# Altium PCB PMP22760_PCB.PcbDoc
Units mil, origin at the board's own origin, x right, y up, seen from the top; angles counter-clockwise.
Board outline 2440.94 x 1102.36 mil, 2 copper layers (Top Layer, Bottom Layer), stack 62 mil thick; 50 components, 22 nets, 102 pads, 106 vias.
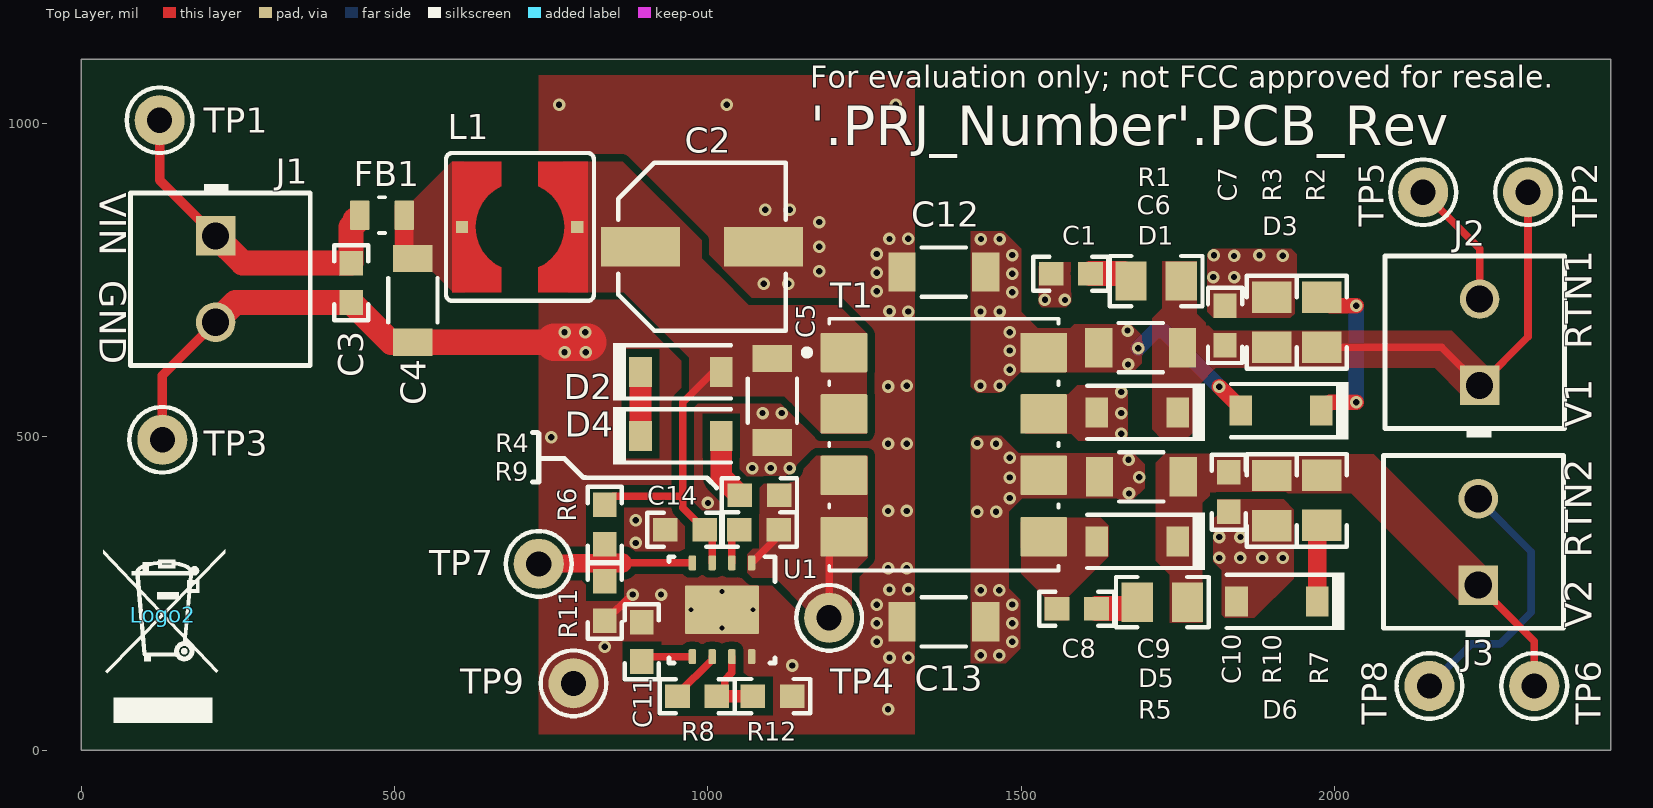
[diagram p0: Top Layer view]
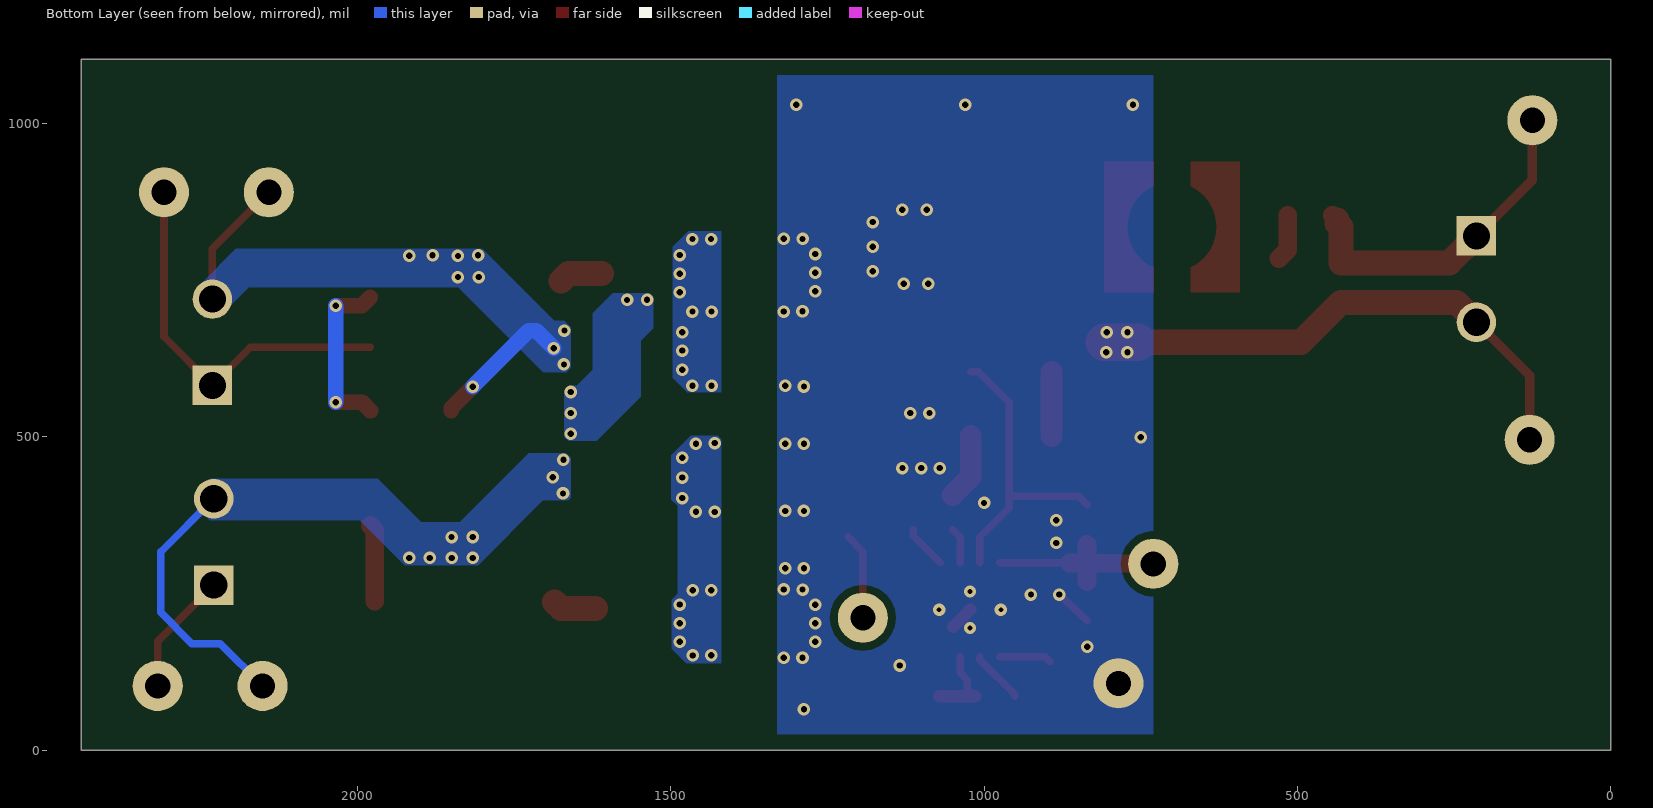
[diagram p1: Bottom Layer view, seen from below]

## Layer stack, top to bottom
Top Solder: solder mask 0.4, Solder Resist, Dk 3.5
Top Layer: signal copper 1.4
Dielectric1: core 59.2, FR-4, Dk 4.8
Bottom Layer: signal copper 1.4
Bottom Solder: solder mask 0.4, Solder Resist, Dk 3.5

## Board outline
0,0 2440.94,0 2440.94,1102.36 0,1102.36

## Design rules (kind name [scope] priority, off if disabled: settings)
AcuteAngle [All] p1: minimum=4.50000000000000E+0001 checktracksonly=FALSE
AssemblyTestPointUsage [All] p1: valid=2
BoardOutlineClearance BoardOutlineClearance_MountingHoles [OnCopper and InComponentClass('Mounting Holes')] p1: gap=39.37 ignorepadtopadclearanceinfootprint=FALSE
BoardOutlineClearance BoardOutlineClearance_Poly [OnCopper and IsPoly] p2: gap=25 ignorepadtopadclearanceinfootprint=FALSE
BoardOutlineClearance [OnCopper and Not InComponentClass('Logo') and not InComponentClass('FiducialMark') and not InRegion(1000,500,4000,800) and not InPoly] p3: gap=50 ignorepadtopadclearanceinfootprint=FALSE
Clearance Clearance_Keepouts [((IsTrack Or IsArc) And Not InPoly) And IsFree and IsKeepOut vs ((IsTrack Or IsArc) And Not InPoly) And IsFree and IsKeepOut] p1: gap=0 ignorepadtopadclearanceinfootprint=FALSE
Clearance Clearance_Poly [InPolygon] p2: gap=12 ignorepadtopadclearanceinfootprint=TRUE
Clearance Clearance_FiducialMark [IsKeepOut and InComponentClass('FiducialMark') vs IsPad and InComponentClass('FiducialMark')] p3: gap=0 ignorepadtopadclearanceinfootprint=FALSE
Clearance [All] p4: gap=7.87 ignorepadtopadclearanceinfootprint=TRUE
ComponentClearance ComponentClearance_MountingHoles_FiducialMarks [InComponentClass('Mounting Holes') vs InComponentClass('FiducialMark')] p1: gap=50 collisioncheckmode=3 verticalgap=10 showdistances=FALSE
ComponentClearance ComponentClearance_Shunt [InComponentClass('Header') vs InComponentClass('Shunt')] p2: gap=0 collisioncheckmode=3 verticalgap=0 showdistances=FALSE
ComponentClearance ComponentClearance_Logo [InComponentClass('Logo')] p3: gap=50 collisioncheckmode=3 verticalgap=10 showdistances=FALSE
ComponentClearance ComponentClearance_ScrewToNut [(HasFootprint('NY PMS 440 0025 PH')) vs (HasFootprint('Keystone_1902C'))] p4: gap=5 collisioncheckmode=3 verticalgap=10 showdistances=FALSE
ComponentClearance ComponentClearance_MountingHoles [InComponentClass('Mounting Holes')] p5: gap=250 collisioncheckmode=3 verticalgap=100000 showdistances=FALSE
ComponentClearance ComponentClearance_SmallPassives [HasFootprint('0201*') or HasFootprint('0402*') or HasFootprint('0508') or HasFootprint('0603*') or HasFootprint('0612') or HasFootprint('0805*') or HasFootprint('0815*') or HasFootprint('0830*') or HasFootprint('1206*') or HasFootprint('1210*') or HasFootprint('1808*') or HasFootprint('1812*') or HasFootprint('1825*') or HasFootprint('2010*') or HasFootprint('2220*') or HasFootprint('2225*') or HasFootprint('2512*') or HasFootprint('2728*') or HasFootprint('3518*') vs HasFootprint('0201*') or HasFootprint('0402*') or HasFootprint('0508') or HasFootprint('0603*') or HasFootprint('0612') or HasFootprint('0805*') or HasFootprint('0815*') or HasFootprint('0830*') or HasFootprint('1206*') or HasFootprint('1210*') or HasFootprint('1808*') or HasFootprint('1812*') or HasFootprint('1825*') or HasFootprint('2010*') or HasFootprint('2220*') or HasFootprint('2225*') or HasFootprint('2512*') or HasFootprint('2728*') or HasFootprint('3518*')] p6: gap=14.96 collisioncheckmode=3 verticalgap=10 showdistances=FALSE
ComponentClearance ComponentClearance_THtoSMT [IsThruComponent vs IsSMTComponent] p7: gap=40 collisioncheckmode=3 verticalgap=30 showdistances=FALSE
ComponentClearance ComponentClearance_THtoTH [IsThruComponent vs IsThruComponent] p8: gap=30 collisioncheckmode=3 verticalgap=30 showdistances=FALSE
ComponentClearance [All] p9: gap=30 collisioncheckmode=3 verticalgap=10 showdistances=FALSE
DiffPairsRouting [All] p1: maxlimit=100 minlimit=10 mostfreqgap=10 toplayer_minwidth=15 toplayer_maxwidth=15 toplayer_prefwidth=15 bottomlayer_minwidth=15 bottomlayer_maxwidth=15 bottomlayer_prefwidth=15 maxuncoupledlength=1000
FabricationTestPointUsage TestPointUsage [All] p1: valid=2 allowmultiple=FALSE
FabricationTestpoint Testpoint [All] p1: side=3 testpointundercomponent=TRUE minsize=40 maxsize=100 preferedsize=60 minholesize=0 maxholesize=40 preferedholesize=32 testpointgrid=1 allowsidetop=TRUE allowsidebottom=TRUE usegrid=TRUE gridtolerance=0.01
FanoutControl Fanout_LCC [IsLCC] p1: bgadir=Out bgaviamode=Centered fanoutstyle=Auto fanoutdirection=Alternating viagrid=1 // Fanout_LCC (Default Rule)
FanoutControl Fanout_BGA [IsBGA] p2: bgadir=Out bgaviamode=Centered fanoutstyle=Auto fanoutdirection=Alternating viagrid=1 // Fanout_BGA (Default Rule)
FanoutControl Fanout_Default [All] p4: bgadir=Out bgaviamode=Centered fanoutstyle=Auto fanoutdirection=Alternating viagrid=1 // Fanout_Default (Default Rule)
FanoutControl Fanout_Small [(CompPinCount < 5)] p5: bgadir=Out bgaviamode=Centered fanoutstyle=Auto fanoutdirection=OutThenIn viagrid=1 // Fanout_Small (Default Rule)
HoleSize [All] p1: absolutevalues=TRUE maxlimit=251 minlimit=7.87 maxpercent=80.000 minpercent=20.000
MinimumAnnularRing MinimumAnnularRing_ThermalPadVias [IsVia and InAnyComponent] p1: minimumring=5.91
MinimumAnnularRing [All] p2: minimumring=5
MinimumSolderMaskSliver MinimumSolderMaskSliver_Logo [InComponentClass('Logo') vs InComponentClass('Logo')] p1: minsoldermaskwidth=0.7
MinimumSolderMaskSliver [All] p2: minsoldermaskwidth=3.94
PlaneClearance [All] p1: clearance=12
PlaneConnect [All] p1: planeconnectstyle=Direct reliefexpansion=10 reliefentries=4 reliefconductorwidth=10 reliefairgap=10
PolygonConnect [All] p1: connectstyle=Direct reliefconductorwidth=10 reliefentries=4 polygonreliefangle="90 Angle" airgapwidth=10
RoutingVias ThermalPadVias [IsVia and InAnyComponent] p1: holewidth=7.87 width=19.68 viastyle="Through Hole" minholewidth=7.87 minwidth=19 maxholewidth=12.99 maxwidth=23.62
RoutingVias [All] p2: holewidth=16 width=34 viastyle="Through Hole" minholewidth=7.87 minwidth=19 maxholewidth=40 maxwidth=65
SilkToBoardRegionClearance [Not ((IsComment or IsDesignator) And (Hide <> 'False')) and not InRegion(1000,500,4000,800)] p1:
SilkToSilkClearance SilkToSilkClearance_Pb-FreeLogo [(HasFootprint('Pb-Free_Overlay_Medium') OR HasFootprint('Pb-Free_Overlay_Small')) vs (HasFootprint('Pb-Free_Overlay_Medium') OR HasFootprint('Pb-Free_Overlay_Small'))] p1: silktosilkclearance=0
SilkToSilkClearance [All] p2: silktosilkclearance=0
SilkToSolderMaskClearance SilkToComponentPadClearance [(IsPad or IsFill or IsRegion) and InAnycomponent] p1: minsilkscreentomaskgap=0 clearancetoexposedcopper=TRUE
SilkToSolderMaskClearance "Silk to Solder Mask Opening" [All] p2: minsilkscreentomaskgap=0 clearancetoexposedcopper=FALSE
SolderMaskExpansion [All] p1: expansion=1.97
UnRoutedNet [All] p1: checkbadconnections=TRUE
Width [All] p1: maxlimit=100 minlimit=6 preferedwidth=10 checkconnectedcopper=TRUE
13 further rules are at their usual default settings.

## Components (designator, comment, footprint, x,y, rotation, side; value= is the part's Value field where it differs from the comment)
C1 "C0603C470J1GACAUTO" 0603 1579.41,760.46 r180 top value=47pF
C2 "EEE-FK1H220P" SM_RADIAL_D 990.57,803.46 r0 top value=22uF
C3 "CGA3E2X7R1H104K080AA" 0603 430.61,745.8 r270 top value=0.1uF
C4 "GCM31CR71E475KA55L" 1206_180 529.03,717.84 r270 top value=4.7uF
C5 "GCM31CR71E475KA55L" 1206_180 1103.09,557.87 r270 top value=4.7uF
C6 "GCM31CR71E475KA55L" 1206_180 1690.94,642.37 r180 top value=4.7uF
C7 "CGA3E2X7R1H104K080AA" 0603 1825.53,677.8 r90 top value=0.1uF
C8 "C0603C470J1GACAUTO" 0603 1588.89,225.72 r180 top value=47pF
C9 "GCM31CR71E475KA55L" 1206_180 1692,436 r180 top value=4.7uF
C10 "CGA3E2X7R1H104K080AA" 0603 1831.49,411.65 r270 top value=0.1uF
C11 "CGA3E2X7R1H473K080AA" 0603 894.58,172.71 r90 top value=0.047uF
C12 "1206J2K00222KXR" 1206_180 1376.67,763.07 r180 top value=2200pF
C13 "1206J2K00222KXR" 1206_180 1376.67,204.4 r180 top value=2200pF
C14 "CGA3E2X7R1H104K080AA" 0603 963.48,351.84 r180 top value=0.1uF
D1 "PMEG6010CEGWJ" SOD-123 1685.53,539 r180 top value=60V
D2 "MMSZ5252BT1G" SOD-123 956.9,603.71 r0 top value=24V
D3 "MMSZ4703-HE3-08" SOD-123 1915,541.74 r180 top value=16V
D4 "PMEG6010CEGWJ" SOD-123 956.9,501.54 r0 top value=60V
D5 "PMEG6010CEGWJ" SOD-123 1685.53,333 r180 top value=60V
D6 "MMSZ4703-HE3-08" SOD-123 1908.34,237.32 r180 top value=16V
FB1 "MPZ2012S101ATD25" FP-MPZ2012S101ATD25_0805-MFG 479.82,853.72 r0 top
J1 "0393570002" MOLEX_39357-0002 214.07,751.7 r270 top
J2 "0393570002" MOLEX_39357-0002 2231.87,650.93 r90 top
J3 "0393570002" MOLEX_39357-0002 2229.74,332.2 r90 top
L1 "744042100" WE-TPC-M1 700,835 r0 top value=10uH
Logo1 "FCC disclaimer" FCC_disclaimer 4534.37,-835.19 r90 top
Logo2 "WEEE logo" WEEE_Minimum 130,216.02 r0 top
R1 "CRCW0805100RJNEA" 0805_HV 1715.53,748.7 r0 top value=100
R2 "CRCW080549R9FKEA" 0805_HV 1980,682.8 r270 top value=49.9
R3 "CRCW08054K99FKEA" 0805_HV 1900,682.8 r270 top value=4.99k
R4 "CRCW06030000Z0EA" 0603 1082.22,406.66 r180 top value=0
R5 "CRCW0805100RJNEA" 0805_HV 1725.53,236.15 r0 top value=100
R6 "CRCW0603332KFKEA" 0603 835.53,360 r90 top value=332k
R7 "CRCW080549R9FKEA" 0805_HV 1980,398.6 r90 top value=49.9
R8 "CRCW0603383KFKEA" 0603 982.87,85.7 r180 top value=383k
R9 "CRCW0603154KFKEA" 0603 1081.59,351.84 r0 top value=154k
R10 "CRCW08054K99FKEA" 0805_HV 1900.39,398.24 r90 top value=4.99k
R11 "CRCW060359K0FKEA" 0603 835.53,237.67 r90 top value=59.0k
R12 "CRCW060312K1FKEA" 0603 1103.24,86.1 r180 top value=12.1k
T1 "ZB1354-AL" FP-ZB1354-AL_SMT8_9MM3_10MM2-MFG 1376.67,487.47 r0 top
TP1 "5000" Keystone5000 124.74,1005.31 r270 top
TP2 "5000" Keystone5000 2309.19,890.39 r90 top
TP3 "" Keystone5001 129.07,495.31 r270 top
TP4 "SW" Keystone5004 1193.6,211.1 r90 top
TP5 "" Keystone5001 2141.87,890.39 r90 top
TP6 "5000" Keystone5000 2319.19,102.25 r90 top
TP7 "EN" Keystone5117 730,297.18 r90 top
TP8 "" Keystone5001 2151.87,102.25 r90 top
TP9 "GND" Keystone5001 785.47,106.53 r90 top
U1 "LM5180QNGURQ1" NGU0008C 1022.54,223.89 r270 top

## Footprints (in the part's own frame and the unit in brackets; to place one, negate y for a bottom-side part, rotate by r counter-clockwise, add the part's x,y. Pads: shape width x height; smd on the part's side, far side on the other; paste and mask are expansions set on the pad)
0603 [mm] "0603 from SM-752 data"
  rect 1x0.95 smd: 1(-0.8,0) 2(0.8,0)
  silkscreen extent -1.52,-0.69 1.52,0.69, body extent -0.87,-0.47 0.87,0.47, height 1
0805_HV [mil] "0805 with 30mil clearance between pads"
  rect 50x63 smd: 1(-40,0) 2(40,0)
  silkscreen extent -74,-40 74,40, body extent -43,-29 43,29, height 57
1206_180 [mm] "1206_180"
  rect 1.1x1.6 smd: 1(-1.7,0) 2(1.7,0)
  silkscreen extent -0.9,-1 0.9,1, body extent -1.75,-0.95 1.75,0.95, height 1.8
FCC_disclaimer [mil]
FP-MPZ2012S101ATD25_0805-MFG [mm]
  rrect13% 0.8x1.2 smd paste+0 mask+0: 1(-0.9,0) 2(0.9,0)
  silkscreen extent -0.13,-0.72 0.13,0.72, body extent -1.4,-0.82 1.4,0.82, height 0.25
FP-ZB1354-AL_SMT8_9MM3_10MM2-MFG [mm]
  rrect6% 1.9x1.6 smd paste+0 mask+0: 1(-4.05,3.735) 2(-4.05,1.245) 3(-4.05,-1.245) 4(-4.05,-3.735) 5(4.05,-3.735) 6(4.05,-1.245) 7(4.05,1.245) 8(4.05,3.735)
  silkscreen extent -5.67,-5.1 4.65,5.1, body extent -5.1,-5.2 5.1,5.2, height 0.25
Keystone5000 [mil] "For Keystone 500x miniature loop terminals"
  round 80 hole 40: 1(0,0)
  silkscreen extent -52,-52 52,52, body extent -49,-49 49,49, height 182
Keystone5001 [mil] "For Keystone 500x miniature loop terminals"
  round 80 hole 40: 1(0,0)
  silkscreen extent -52,-52 52,52, body extent -49,-49 49,49, height 182
Keystone5004 [mil] "For Keystone 500x miniature loop terminals"
  round 80 hole 40: 1(0,0)
  silkscreen extent -52,-52 52,52, body extent -49,-49 49,49, height 182
Keystone5117 [mil] "For Keystone 500x miniature loop terminals"
  round 80 hole 40: 1(0,0)
  silkscreen extent -52,-52 52,52, body extent -49,-49 49,49, height 182
MOLEX_39357-0002 [mm] "Terminal Block, 3.5 mm, 2x1, TH"
  rect 1.6x1.6 hole 1.1: 1(-1.75,0)
  round 1.6 hole 1.1: 2(1.75,0)
  silkscreen extent -3.86,-3.45 3.5,3.84, body extent -3.55,-3.45 3.56,3.84, height 8.51
NGU0008C [mm] "SON, 8-Leads, Body 4x4mm, Pitch 0.8mm"
  rrect33% 0.6x0.3 smd: 1(-1.9,1.2) 2(-1.9,0.4) 3(-1.9,-0.4) 4(-1.9,-1.2) 5(1.9,-1.2) 6(1.9,-0.4) 7(1.9,0.4) 8(1.9,1.2)
  rrect8% 1.75x1.31 on Top Paste: 9(0,0.755) 9(0,-0.755)
  rrect5% 1.98x3 smd paste-1.5: 9(0,0)
  silkscreen extent -2.15,-2.15 2.15,2.15, body extent -2,-2 2,2, height 0.77
SM_RADIAL_D [mm] "6.3 x 5.8mm:  Panasonic D"
  rect 3.2x1.6 smd: 1(-2.5,0) 2(2.5,0)
  silkscreen extent -3.4,-3.4 3.4,3.4, body extent -3.4,-3.4 3.4,3.4, height 6.1
SOD-123 [mm] "On Semi recommended land pattern"
  rect 0.915x1.22 smd: 1(-1.637,0) 2(1.637,0)
  silkscreen extent -2.74,-1.17 2.03,1.17, body extent -1.93,-0.9 1.93,0.9, height 1.35
WE-TPC-M1 [mm] "Wurth Elektronik recommended land pattern"
  rect 0.5x0.5 smd: 1(-2.35,0) 2(2.325,0)
  Top Layer region: 0.75,1.64 1.005,1.504 1.279,1.279 1.504,1.005 1.671,0.692 1.774,0.353 1.809,0 1.774,-0.353 1.671,-0.692 1.504,-1.005 1.279,-1.279 1.005,-1.504 0.75,-1.64 0.75,-2.65 2.75,-2.65 2.75,2.65 0.75,2.65
  Top Layer region: -0.75,1.64 -1.005,1.504 -1.279,1.279 -1.504,1.005 -1.671,0.692 -1.774,0.353 -1.809,0 -1.774,-0.353 -1.671,-0.692 -1.504,-1.005 -1.279,-1.279 -1.005,-1.504 -0.75,-1.64 -0.75,-2.65 -2.75,-2.65 -2.75,2.65 -0.75,2.65
  silkscreen extent -3,-3 3,3, body extent -2.5,-2.5 2.5,2.5, height 2
WEEE_Minimum [mil] "WEEElie bin"
  silkscreen extent -95,-172 99,104

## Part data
C1 C8: library part CMP-0085572-1, "CAP, CERM, 47 pF, 100 V,+/- 5%, C0G/NP0, AEC-Q200 Grade 1, 0603", Cap_Case=0603, Manufacturer=Kemet, TempCo=C0G/NP0, Tolerance_%=5%, Value2=100V, ValueDisplayed=47pF
C2: library part CMP-0011179-2, "CAP, AL, 22 uF, 50 V, +/- 20%, 0.88 ohm, AEC-Q200 Grade 2, SMD", Cap_Case=D, Manufacturer=Panasonic, Supplier Part Number 1=PCE3811CT-ND, Tolerance_%=20%, Value1="0.88 ohm", Value2=50V, ValueDisplayed=22uF
C3 C7 C10 C14: library part CMP-0007078-4, "CAP, CERM, 0.1 uF, 50 V, +/- 10%, X7R, AEC-Q200 Grade 1, 0603", Cap_Case=0603, Manufacturer=TDK, Supplier Part Number 1=445-5666-1-ND, TempCo=X7R, Tolerance_%=10%, Value1="0.0296 ohm", Value2=50V, ValueDisplayed=0.1uF
C4 C5 C6 C9: library part CMP-0082300-1, "CAP, CERM, 4.7 µF, 25 V,+/- 10%, X7R, AEC-Q200 Grade 1, 1206", Cap_Case=1206, Manufacturer=MuRata, Supplier Part Number 1=490-4794-1-ND, TempCo=X7R, Tolerance_%=10%, Value2=25V, ValueDisplayed=4.7µF
C11: library part CMP-0007079-4, "CAP, CERM, 0.047 uF, 50 V, +/- 10%, X7R, AEC-Q200 Grade 1, 0603", Cap_Case=0603, Manufacturer=TDK, Supplier Part Number 1=445-5664-1-ND, TempCo=X7R, Tolerance_%=10%, Value1="0.049007 ohm", Value2=50V, ValueDisplayed=0.047uF
C12 C13: library part CMP-0077201-1, "CAP, CERM, 2200 pF, 2000 V,+/- 10%, X7R, AEC-Q200 Grade 1, 1206", Cap_Case=1206, Manufacturer="Knowles Capacitors", Supplier Part Number 1=1206J2K00222KXR-ND, TempCo=X7R, Tolerance_%=10%, Value2=2000V, ValueDisplayed=2200pF
D1 D4 D5: library part CMP-0079239-2, "Diode, Schottky, 60 V, 1 A, AEC-Q101, SOD-123", Manufacturer=Nexperia, Value1=1A, Value2=0.66V
D2: library part CMP-0005771-4, "Diode, Zener, 24 V, 500 mW, AEC-Q101, SOD-123", Manufacturer="ON Semiconductor", Power_W=500mW, Value1=0.5W
D3 D6: library part CMP-0077576-3, "Diode, Zener, 16 V, 500 mW, AEC-Q101, SOD-123", Manufacturer=Vishay-Semiconductor, Power_W=500mW, Value1=0.5W
FB1: library part CMP-0089947-1, "100 Ohms @ 100MHz 1 Power Line Ferrite Bead 0805 (2012 Metric) 4A 20mOhm", Digikey Part Number=445-172903-1-ND, Impedance At Frequency="100O @ 100MHz", Manufacturer=TDK, Mouser Part Number=810-MPZ2012S101ATD25, Operating Temperature Range="-55°C to +125°C", Test Frequency=100MHz, Tolerance_%=25%
J1 J2 J3: library part CMP-0055341-2, "Terminal Block, 3.5 mm, 2x1, Tin, TH", Manufacturer=Molex, Supplier Part Number 1=WM7877-ND
L1: library part CMP-0063804-1, "Inductor, Shielded Drum Core, Ferrite, 10 uH, 1 A, 0.12 ohm, SMD", Manufacturer="Wurth Elektronik", Supplier Part Number 1=732-1025-1-ND, Value1="0.12 ohm", Value2=1A, ValueDisplayed=10uH
Logo1: library part CMP-0074847-1, "FCC_disclaimer"
Logo2: library part CMP-0074769-1
R1 R5: library part CMP-0020445-3, "RES, 100, 5%, 0.125 W, AEC-Q200 Grade 0, 0805", Manufacturer=Vishay-Dale, Power_W=125mW, Supplier Part Number 1=541-100ACT-ND, TempCo="200 ppm/C", Tolerance_%=5%, Value2=0.125W, Value_Code=100R, ValueDisplayed=100
R2 R7: library part CMP-0021284-3, "RES, 49.9, 1%, 0.125 W, AEC-Q200 Grade 0, 0805", Manufacturer=Vishay-Dale, Power_W=125mW, Supplier Part Number 1=541-49.9CCT-ND, TempCo="100 ppm/C", Tolerance_%=1%, Value2=0.125W, Value_Code=49R9, ValueDisplayed=49.9
R3 R10: library part CMP-0021294-3, "RES, 4.99 k, 1%, 0.125 W, AEC-Q200 Grade 0, 0805", Manufacturer=Vishay-Dale, Power_W=125mW, Supplier Part Number 1=541-4.99KCCT-ND, TempCo="100 ppm/C", Tolerance_%=1%, Value2=0.125W, Value_Code=4k99, ValueDisplayed=4.99k
R4: library part CMP-0025697-4, "RES, 0, 5%, 0.1 W, AEC-Q200 Grade 0, 0603", Manufacturer=Vishay-Dale, Power_W=100mW, Supplier Part Number 1=541-0.0GCT-ND, TempCo="200 ppm/C", Tolerance_%=5%, Value2=0.1W, Value_Code=0000, ValueDisplayed=0
R6: library part CMP-0022336-4, "RES, 332 k, 1%, 0.1 W, AEC-Q200 Grade 0, 0603", Manufacturer=Vishay-Dale, Power_W=100mW, Supplier Part Number 1=541-332KHCT-ND, TempCo="100 ppm/C", Tolerance_%=1%, Value2=0.1W, Value_Code=332k
R8: library part CMP-0022362-4, "RES, 383 k, 1%, 0.1 W, AEC-Q200 Grade 0, 0603", Manufacturer=Vishay-Dale, Power_W=100mW, Supplier Part Number 1=541-383KHCT-ND, TempCo="100 ppm/C", Tolerance_%=1%, Value2=0.1W, Value_Code=383k
R9: library part CMP-0022062-4, "RES, 154 k, 1%, 0.1 W, AEC-Q200 Grade 0, 0603", Manufacturer=Vishay-Dale, Power_W=100mW, Supplier Part Number 1=541-154KHCT-ND, TempCo="100 ppm/C", Tolerance_%=1%, Value2=0.1W, Value_Code=154k
R11: library part CMP-0022507-4, "RES, 59.0 k, 1%, 0.1 W, AEC-Q200 Grade 0, 0603", Manufacturer=Vishay-Dale, Power_W=100mW, Supplier Part Number 1=541-59.0KHCT-ND, TempCo="100 ppm/C", Tolerance_%=1%, Value2=0.1W, Value_Code=59k0, ValueDisplayed=59.0k
R12: library part CMP-0022030-4, "RES, 12.1 k, 1%, 0.1 W, AEC-Q200 Grade 0, 0603", Manufacturer=Vishay-Dale, Power_W=100mW, Supplier Part Number 1=541-12.1KHCT-ND, TempCo="100 ppm/C", Tolerance_%=1%, Value2=0.1W, Value_Code=12k1, ValueDisplayed=12.1k
T1: library part CMP-0090909-2, "FLYBACK TRANSFORMER SMD 8 Pin 10-16Vin 200-350kHz, Output 15.7/.185A x 2 Turns Ratio 1:1:1", Frequency_Fixed=200-350kHz, Manufacturer=Coilcraft, Operating Temperature Range=to, Voltage_Isolation_Vrms=1500Vrms
TP1 TP2 TP6: library part CMP-0055137-1, "Test Point, Miniature, Red, TH", Color=Red, Manufacturer=Keystone, Supplier Part Number 1=36-5000-ND
TP3 TP5 TP8 TP9: library part CMP-0055138-1, "Test Point, Miniature, Black, TH", Color=Black, Manufacturer=Keystone, PartNumber=5001, Supplier Part Number 1=36-5001-ND
TP4: library part CMP-0055141-1, "Test Point, Miniature, Yellow, TH", Color=Yellow, Manufacturer=Keystone, PartNumber=5004, Supplier Part Number 1=36-5004-ND
TP7: library part CMP-0055154-1, "Test Point, Miniature, Blue, TH", Color=Blue, Manufacturer=Keystone, PartNumber=5117, Supplier Part Number 1=36-5117-ND
U1: library part CMP-0078633-2, "70-V PSR Flyback Converter With 100-V, 1.2-A Power Switch and Ultra-Low IQ, NGU0008C (WSON-8)", Alternate Manufacturer="Texas Instruments", Alternate PartNumber=LM5180QNGUTQ1

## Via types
v1: diameter 20, hole 10, Top Layer to Bottom Layer, 102 vias
v2: diameter 19.68, hole 7.87, Top Layer to Bottom Layer, 4 vias

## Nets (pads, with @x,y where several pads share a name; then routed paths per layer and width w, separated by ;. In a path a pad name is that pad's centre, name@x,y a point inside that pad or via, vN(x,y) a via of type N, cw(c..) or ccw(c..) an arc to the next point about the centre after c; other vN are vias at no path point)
GND: C2.2 C3.2 C4.2 C5.2 C11.2 C12.2 C13.2 C14.2 J1.2 R11.1 R12.1 TP3.1 TP9.1 U1.8 U1.9@1022.54,223.89 | length 957.6
  Top Layer w12: R11.1 v1(880,248.18) v1@880,250.65
  Top Layer w15: TP3.1 129.07,597.8 J1.2
  Top Layer w20: U1.9@1022.54,223.89 U1.9@1049.25,197.18
  Top Layer w40: J1.2 245.57,714.31 C3.2 494,650.91 C4.2 754.78,650.91
  Top Layer w60: 754.78,650.91 805,650.91 808.27,650.91
  other v1: 1287.64,65 1134.74,134.92 1289.91,147.12 1319.74,147.12 835.53,165 1269.74,172.71 1269.74,202.24 1269.74,232.07 925.28,248.18 1289.74,256.1 1319.74,256.37 1287.64,290 1317.47,290 884.74,330.59 884.74,366.84 1287.64,381.65 1317.47,381.65 1000,394.45 1071,450.03 1100.52,450.03 1130.35,450.03 1287.64,488.97 1317.47,488.97 750,499.32 1087.34,537.87 1118.09,537.87 1287.64,580.29 1317.47,581.5 771.21,635 805,635 771.21,666.77 804.3,666.77 1320,700 1289.91,700.56 1269.57,732.38 1089,744.4 1128.37,744.4 1269.74,761.96 1177.58,764.09 1269.74,791.79 1177.58,803.46 1289.74,815.82 1319.74,816.1 1177.58,842.83 1091.36,862.51 1130.73,862.51 762.5,1030 1030,1030 1300,1030
  other v2: 1022.54,194.76 973.32,223.89 1071.75,223.89 1022.54,253.03
NetC1_1: C1.1 R1.1 | length 69.5
  Top Layer w40: C1.1 1663.76,760.46 R1.1
NetC1_2: C1.2 D1.2 T1.7
  other v1: 1660,505 1660,537.87 1660,571.53 1570,718.43 1538,718.65
NetC2_1: C2.1 C5.1 C14.1 D2.2 L1.2 R6.2 T1.1 T1.2 U1.3 | length 487.2
  Top Layer w12: R6.2 849.03,405 960,405 ; U1.3 1006.79,340.03 C14.1 960,386.82 960,405 ; D2.2 1008.93,603.71 960,554.78 960,405
NetC3_1: C3.1 FB1.1 J1.1 TP1.1 | length 538.3
  Top Layer w15: TP1.1 124.74,909.93 J1.1
  Top Layer w30: FB1.1@436.51,845.85 FB1.1
  Top Layer w40: J1.1 257.37,777.3 C3.1 430.61,835 436.51,840.91 FB1.1@436.51,845.85
NetC4_1: C4.1 FB1.2 L1.1 | length 74.7
  Top Layer w30: FB1.2 515.25,798.55 C4.1
NetC6_1: C6.1 C7.1 D1.1 J2.1 R1.2 R2.2 R3.2 TP2.1 | length 617.4
  Top Layer w12: R2.2 2171.1,642.8 J2.1 2309.19,659.36 TP2.1
NetC8_1: C8.1 R5.1 | length 69.5
  Top Layer w40: C8.1 1675.09,225.72 R5.1
NetC8_2: C8.2 D5.2 T1.5
NetC9_1: C9.1 C10.1 D5.1 J3.1 R5.2 R7.2 R10.2 TP6.1 | length 198.1
  Top Layer w12: J3.1 2319.19,173.86 TP6.1
NetC11_1: C11.1 U1.5 | length 84
  Top Layer w12: C11.1 902.46,149.09 U1.5
NetD2_1: D2.1 D4.1 | length 102.2
  Top Layer w35: D4.1 D2.1
NetD3_1: D3.1 R2.1 | length 275.9
  Top Layer w25: D3.1 1992.73,555 v1(2035,555) ; R2.1 1993.5,709.3 v1(2035,709.3)
  Bottom Layer w25: v1(2035,555) v1(2035,709.3)
NetD4_2: D4.2 R4.2 | length 107
  Top Layer w35: D4.2 1021.37,436.02 R4.2
NetD6_1: D6.1 R7.1 | length 124.3
  Top Layer w30: D6.1 1972.81,351.41 R7.1
NetR4_1: R4.1 R9.2 T1.3 T1.4 TP4.1 U1.1 | length 210.2
  Top Layer w12: U1.1 1113.09,342 R9.2 ; TP4.1 1193.6,316.81 T1.4
NetR6_1: R6.1 R11.2 TP7.1 U1.4 | length 303.7
  Top Layer w12: 865.05,298.7 U1.4
  Top Layer w30: TP7.1 833.99,298.35 835.2,298.37 835.5,298.37 ; R11.2 835.53,298.37 ; R6.1 835.53,298.37 ; 864.07,298.7 835.87,298.38 835.53,298.37
NetR8_1: R8.1 R12.2 U1.7 | length 130.8
  Top Layer w12: R8.1 1026.61,97.95 1026.61,111.61 1038.28,123.28 U1.7
  Top Layer w20: R8.1 1071.35,85.7 R12.2
NetR8_2: R8.2 U1.6 | length 86.3
  Top Layer w12: R8.2 951.37,88.98 1006.79,144.39 U1.6
NetR9_1: R9.1 U1.2 | length 58
  Top Layer w12: U1.2 1038.28,340.03 R9.1
RTN1: C6.2 C7.2 C12.1 D3.2 J2.2 R3.1 T1.8 TP5.1 | length 438.4
  Top Layer w12: TP5.1 2231.87,800.39 J2.2
  Top Layer w25: v1(1816.49,580) 1850.53,545.96 D3.2
  Bottom Layer w25: v1(1687.03,641.55) 1715.03,669.55 1726.95,669.55 v1(1816.49,580)
  other v1: 1435,581.5 1465.7,581.5 1481.87,607 1670.72,615.55 1481.87,637.74 1481.87,666.77 1670.03,669.55 1435,700 1465.7,700 1485.7,730.63 1806.83,755 1840,755 1485.7,760.46 1840,788.7 1917.69,789.01 1485.87,790.04 1807.87,790 1880.54,790 1435.87,815.63 1465.7,815.63
RTN2: C9.2 C10.2 C13.1 D6.2 J3.2 R10.1 T1.6 TP8.1 | length 428.1
  Bottom Layer w12: TP8.1 2219.61,170 2265,170 2314.74,219.74 2314.74,316.1 J3.2
  other v1: 1435.59,151.23 1465.17,151.06 1485.87,172.71 1485.87,202.54 1486.04,232.12 1435.59,255.17 1465.17,255 1816.49,306.65 1850,306.65 1885,306.65 1917.69,306.65 1816.49,340.03 1850.19,340 1430,380 1460,380.39 1481.87,402.2 1672.22,409.56 1481.87,435 1688.54,435.56 1671.54,463.56 1481.87,466.64 1460,488.97 1430,490
pads on no net: U1.9@992.81,223.89 U1.9@1052.26,223.89

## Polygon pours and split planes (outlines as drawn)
RTN1 on Top Layer "TOP_LAYER_RTN1_P100" (solid, remove dead copper, pour order 100): 1806.83,690 1806.83,690.16 1796.99,700 1796.99,792.46 1805,800.47 1931.32,800.47 1940,791.79 1940,700 1930,690
NetC6_1 on Top Layer "TOP_LAYER_NETC6_1_P096" (solid, remove dead copper, pour order 96): 1763.46,496.5 1725.3,496.5 1724.71,496.35 1708.99,512.07 1708.99,688.99 1725.3,705.3 1725.3,780.11 1780.47,780.11 1780.59,696.25 1807.28,669.55 2187.45,669.55 2250,607 2204.37,561.37 2204.37,565.63 2160,610 1810.71,610 1785,584.29 1785,515.88
NetC9_1 on Top Layer "TOP_LAYER_NETC9_1_P092" (solid, remove dead copper, pour order 92): 1789.53,203.22 1737.5,203.22 1737.5,280 1736.97,280 1715,301.97 1715,458.4 1730,473.4 1730.8,472.6 2020,472.6 2020.36,472.24 2062.76,472.24 2255,280 2210,235 2202,235 2027,410 1804.53,410 1789.53,395
NetC9_1 on Top Layer "TOP_LAYER_NETC9_1_P090" (solid, remove dead copper, pour order 90): 1789.53,203.22
RTN2 on Top Layer "TOP_LAYER_RTN2_P088" (solid, remove dead copper, pour order 88): 1812.79,400 1812.79,374.84 1807.87,369.92 1807.87,339.46 1806.75,338.35 1806.75,300.25 1820,287 1820,216.1 1825,211.1 1872.4,211.1 1935,273.69 1935,383.93 1918.93,400
RTN2 on Top Layer "TOP_LAYER_RTN2_P084" (solid, remove dead copper, pour order 84): 1420,138.26 1420,496.46 1425,501.46 1468.54,501.46 1496.6,473.4 1680,473.4 1696.99,456.42 1696.99,418.01 1677.58,398.6 1650,398.6 1650,400.81 1651.4,402.2 1501.82,402.2 1480,380.39 1480,258.48 1498.48,240 1498.48,161.53 1475.21,138.26
NetC8_2 on Top Layer "TOP_LAYER_NETC8_2_P082" (solid, remove dead copper, pour order 82): 1499,370.55 1627.21,370.55 1640,357.76 1640,309.42 1575,244.42 1575,207.02 1538,207.02 1538,243.72 1500.06,281.65
RTN2 on Top Layer "TOP_LAYER_RTN2_P078" (solid, remove dead copper, pour order 78): 1499,471
NetC1_2 on Top Layer "TOP_LAYER_NETC1_2_P076" (solid, remove dead copper, pour order 76): 1579.58,778.97 1527.87,779.16 1527.87,712.13 1533,707 1574.07,707 1579.76,712.7
RTN1 on Top Layer "TOP_LAYER_RTN1_P066" (solid, remove dead copper, pour order 66): 1420,828.05 1420,580.29 1430,570.29 1465.93,570.29 1498.48,603.03 1645.16,603.03 1678.06,603.03 1698,622.97 1698,657.02 1675.27,679.75 1584.94,679.75 1578.29,673.1 1526.68,673.1 1500,699.77 1500,800 1471.95,828.05
RTN1 on Top Layer "TOP_LAYER_RTN1_P064" (solid, remove dead copper, pour order 64): 1585.63,666.77
RTN1 on Top Layer "TOP_LAYER_RTN1_P062" (solid, remove dead copper, pour order 62): 1641.53,690
NetC1_2 on Top Layer "TOP_LAYER_NETC1_2_P052" (solid, remove dead copper, pour order 52): 1663.76,493.7 1663.76,494.25 1670,500.49 1670,576.5 1665,581.5 1610,581.5 1609.47,582.03 1589.64,582.03 1575.37,567.76 1500.06,567.76 1500,505 1579.76,505 1591.07,493.7
GND on Top Layer "TOP_LAYER_GND_P050" (solid, remove dead copper, pour order 50): 1330,0 1330,1102.36 730,1102.36 730,0
RTN1 on Top Layer "TOP_LAYER_RTN1_P018" (solid, remove dead copper, pour order 18): 1500,506.57
RTN1 on Top Layer "TOP_LAYER_RTN1_P016" (solid, remove dead copper, pour order 16): 1500,506.57
NetC2_1 on Top Layer "TOP_LAYER_NETC2_1_P006" (solid, remove dead copper, pour order 6): 768.9,939.33 864.15,939.33 990,813.48 990,785.3 1065.3,710 1208.83,710 1253.83,665 1253.83,505 1181.57,505 1121.57,565 973.79,565 970,561.21 970,626.09 865.42,730.67 768.9,730.67 775,736.77 775,893.9 768.9,900
NetC4_1 on Top Layer "TOP_LAYER_NETC4_1_P004" (solid, remove dead copper, pour order 4): 500,791.79 532.3,791.79 591.73,732.36 591.73,730.67 610.67,730.67 616.23,736.23 616.23,933.77 610,940 609.33,939.33 590.91,939.33 521.57,870 500,870
NetC4_1 on Top Layer "TOP_LAYER_NETC4_1_P002" (solid, remove dead copper, pour order 2): 540,760
NetR4_1 on Top Layer "TOP_LAYER_NETR4_1_P000" (solid, remove dead copper, pour order 0): 1173.37,470 1128.37,425 1128.01,425.36 1089.27,425.36 1082.22,418.31 1082.22,331.53 1062.89,312.2 1062.89,282.8 1071.07,274.61 1107.59,274.61 1157.2,225 1228.69,225 1230,226.31 1230,281.65 1255,306.65 1255,470
RTN1 on Bottom Layer "BOTTOM_LAYER_RTN1_P098" (solid, remove dead copper, pour order 98): 1659.9,674.9 1670,685 1685.83,685 1800.83,800 2194.4,800 2250,744.4 2250,705.3 2241.32,705.3 2225,688.99 2208.68,705.3 2207.15,705.3 2173.63,738.83 1839.68,738.83 1703.88,603.03 1666.94,603.03 1659.9,610.07
RTN2 on Bottom Layer "BOTTOM_LAYER_RTN2_P094" (solid, remove dead copper, pour order 94): 1666.66,473.4 1659.9,466.64 1659.9,402.48 1663.79,398.6 1704.27,398.6 1807.87,295 1925,295 1996.84,366.84 2236,366.84 2250,380.84 2250,418.31 2235,433.31 1968.31,433.31 1898.43,363.43 1836.78,363.43 1726.81,473.4
RTN2 on Bottom Layer "BOTTOM_LAYER_RTN2_P086" (solid, remove dead copper, pour order 86): 1420,138.26 1420,496.46 1425,501.46 1468.54,501.46 1499.09,470.91 1499.09,399.47 1489.24,389.63 1489.24,249.24 1498.48,240 1498.48,161.53 1475.21,138.26
RTN1 on Bottom Layer "BOTTOM_LAYER_RTN1_P074" (solid, remove dead copper, pour order 74): 1420,828.05 1420,570.93 1472.35,570.93 1473,570.29 1497,594.29 1497,803 1471.95,828.05
NetC1_2 on Bottom Layer "BOTTOM_LAYER_NETC1_2_P072" (solid, remove dead copper, pour order 72): 1593,729 1625,697 1625,607 1650.5,581.5 1665,581.5 1670,576.5 1670,499.94 1663.76,493.7 1618.3,493.7 1547.91,564.09 1547.91,653.18 1528,673.1 1528,723.24 1533.76,729
RTN1 on Bottom Layer "BOTTOM_LAYER_RTN1_P070" (solid, remove dead copper, pour order 70): 2045.74,763.07
GND on Bottom Layer "BOTTOM_LAYER_GND_P008" (solid, remove dead copper, pour order 8): 1330,0 1330,1102.36 730,1102.36 730,0

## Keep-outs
Keep-Out Layer:
  text ".Layer_Name" at 577,-858.49 h60

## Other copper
Top Layer:
  text ".Layer_Name" at 577,-858.49 h60
Bottom Layer:
  pour cut-out: 1330,688.26
  text ".Layer_Name" at 577,-858.49 h60

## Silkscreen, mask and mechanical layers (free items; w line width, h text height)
Top Overlay:
  lines w8: 720,427.76 730,427.76 730,505.11 728.23,506.88 720,506.88 ; 730,465 771.21,465 801.21,435 804.3,435 998.65,434.17 1014.01,418.82 1014.01,418.3
  text "'.PRJ_Number'.PCB_Rev" at 1163.23,945 h108.27
  text "VIN" at 15,889.49 h72.83 r270
  text "GND" at 15,750 h72.83 r270
  text "RTN1" at 2425,640 h72.83 r90
  text "V1" at 2425,515.37 h72.83 r90
  text "RTN2" at 2425,306.84 h72.83 r90
  text "V2" at 2425,195 h72.83 r90
  text ".Layer_Name" at 577,-858.49 h60
Bottom Overlay:
  text ".Layer_Name" at 577,-858.49 h60
Top Paste:
  text ".Layer_Name" at 577,-858.49 h60
Bottom Paste:
  text ".Layer_Name" at 577,-858.49 h60
Top Solder:
  text ".Layer_Name" at 577,-858.49 h60
  text ".Layer_Name" at 577,-858.49 h60
Bottom Solder:
  rectangle: 1420,399.56 1465,470
  rectangle: 1285,399.56 1330,470
  rectangle: 1420,600 1465,670.44
  rectangle: 1285,600 1330,670.44
  text ".Layer_Name" at 577,-858.49 h60
Drill Guide:
  text ".Layer_Name" at 577,-858.49 h60
M1 Board Outline:
  lines w8: 0,0 0,1102.36 2440.94,1102.36 2440.94,0 0,0
  lines w10: 0,0 0,1102.36 2440.94,1102.36 2440.94,0 0,0
  text ".Layer_Name" at 577,-858.49 h60
M2 Board Dimensions:
  rectangle: 0,-275 125,-150
  rectangle: 125,-400 500,-275
  lines w7: 0,-275 1000,-275 ; 125,-400 125,-150 ; 250,-400 250,-150 ; 500,-400 500,-150 ; 750,-400 750,-150 ; 0,-400 1000,-400 1000,-150 0,-150 0,-400
  text ".Layer_Name" at 577,-858.49 h60
M3 3D STEP Top:
  text ".Layer_Name" at 577,-858.49 h60
M4 3D STEP Bottom:
  text ".Layer_Name" at 577,-858.49 h60
M5 Assembly Top:
  lines w10: -292,-930.17 6308,-930.17 ; -292,-726.83 6310,-726.83 ; -292,-523.5 -292,-1133.5 3713,-1133.5 6310,-1133.5 6310,-523.5 -291.5,-523.5 -291.5,-1133.5 1284,-1133.5 ; 2173,-1133.5 2173,-523.5 ; 3440,-726.83 3440,-523.5 ; 4280,-726.83 4280,-523.5 ; 4902,-1140 4902,-937.17
  text "PMP22760A" at 1160,945 h110
  text "COMPONENTS MARKED 'DNP' SHOULD NOT BE POPULATED." at 1153.5,-318.5 h60
  text "ASSEMBLY VARIANT:" at 1153,-434 h60
  text ".VariantName" at 2189,-434 h60
  text "PCB VIEWED FROM TOP SIDE" at -228.5,-655.67 h60
  text "BOARD #:" at 2248,-655.67 h60
  text ".PRJ_Number" at 2793.5,-655.67 h60
  text "REV:" at 3638,-655.67 h60
  text ".PCB_Rev" at 3929.5,-655.67 h60
  text "SVN REV:" at 4476,-655.67 h60
  text ".VersionControl_RevNumber" at 4982,-655.67 h60
  text "TID #:" at 2248,-859 h60
  text ".TID" at 2793.5,-859 h60
  text "PLOT NAME =" at -228.5,-1064.34 h60
  text ".plot_File_Name" at 577,-1064.34 h60
  text "GENERATED    :" at 2250,-1064.34 h60
  text ".Print_Date" at 3119.5,-1064.34 h60
  text ".Print_Time" at 3848.5,-1064.34 h60
  text "TEXAS INSTRUMENTS" at 5113,-1064.34 h60
M6 Assembly Bottom:
  lines w10: -292.5,-727.33 6309.5,-727.33 ; -290.5,-930.67 6309.5,-930.67 ; 1115.5,-1140.5 1115.5,-937.67 ; 1737.5,-727.33 1737.5,-524 ; 2577.5,-727.33 2577.5,-524 ; 3844.5,-1134 3844.5,-524 ; 4733.5,-1134 6309,-1134 6309,-524 -292.5,-524 -292.5,-1134 2304.5,-1134 6309.5,-1134 6309.5,-524
  text "COMPONENTS MARKED 'DNP' SHOULD NOT BE POPULATED." at 6102,-318 h60
  text ".VariantName" at 5058,-434 h60
  text "ASSEMBLY VARIANT:" at 6097,-434 h60
  text ".VersionControl_RevNumber" at 1035.5,-656.17 h60
  text "SVN REV:" at 1541.5,-656.17 h60
  text ".PCB_Rev" at 2088,-656.17 h60
  text "REV:" at 2379.5,-656.17 h60
  text ".PRJ_Number" at 3224,-656.17 h60
  text "BOARD #:" at 3769.5,-656.17 h60
  text "PCB VIEWED FROM BOTTOM SIDE" at 6246,-656.17 h60
  text ".TID" at 3224,-859.5 h60
  text "TID #:" at 3769.5,-859.5 h60
  text "TEXAS INSTRUMENTS" at 904.5,-1064.84 h60
  text ".Print_Time" at 2169,-1064.84 h60
  text ".Print_Date" at 2898,-1064.84 h60
  text "GENERATED    :" at 3767.5,-1064.84 h60
  text ".plot_File_Name" at 5440.5,-1064.84 h60
  text "PLOT NAME =" at 6246,-1064.84 h60
M9 Title Sheet:
  drawing of 57 lines, arcs and shapes, not listed
  text "1" at 739.84,8036.5 h70
  text "2" at 3235.5,8036.5 h70
  text "3" at 5724.84,8036.5 h70
  text "4" at 8231.51,8036.5 h70
  text "5" at 10730.5,8036.5 h70
  text "6" at 13235.5,8036.5 h70
  text "A" at -416.5,6893.5 h70
  text "A" at 14383.5,6893.5 h70
  text "B" at -416.5,4513.5 h70
  text "B" at 14383.5,4513.5 h70
  text "C" at -416.5,2138.5 h70
  text "C" at 14383.5,2138.5 h70
  text "PROJECT TITLE:" at 11343.5,277.5 h45
  text ".PRJ_Title" at 11393.5,144.17 h70
  text "DESIGNED FOR:" at 11343.5,-23.5 h45
  text ".PRJ_Customer" at 11393.5,-163.5 h70
  text "D" at -416.5,-231.5 h70
  text "D" at 14383.5,-231.5 h70
  text "FILE NAME:" at 11343.5,-323.5 h45
  text ".PCB_File_Name_No_Path" at 11393.5,-443.5 h70
  text "Texas Instruments (TI) and/or its licensors do not warrant the accuracy or completeness of this specification" at 6374,-605.34 h45
  text "ENGINEER:" at 11343.5,-613.5 h45
  text "LAYOUT BY:" at 12848.5,-613.5 h45
  text "or any information contained therein. TI and/or its licensors do not warrant that this design will meet" at 6329.01,-718 h45
  text ".PRJ_Engineer" at 11393.5,-768.49 h70
  text ".PCB_Layout" at 12899,-768.49 h70
  text "the specifications, will be suitable for your application or fit for any particular purpose, or will operate in" at 6329.01,-830.67 h45
  text ".Layer_Name" at 577,-858.49 h60
  text "ALTIUM DESIGNER VERSION:" at 12848.5,-923.5 h45
  text "an implementation. TI and/or its licensors do not warrant that the design is production worthy. You should" at 6329.01,-943.33 h45
  text "completely validate and test your design implementation to confirm the system functionality for your application." at 6374,-1056 h45
  text ".print_Scale" at 11393.5,-1056.83 h70
  text ".Application_BuildNumber" at 12899,-1056.83 h70
  text "1" at 739.84,-1263.5 h70
  text "2" at 3235.5,-1263.5 h70
  text "3" at 5724.84,-1263.5 h70
  text "4" at 8231.51,-1263.5 h70
  text "5" at 10730.5,-1263.5 h70
  text "6" at 13235.5,-1263.5 h70
M10 Fab Notes:
  drawing of 189 lines, arcs and shapes, not listed
  text "DESIGN INFORMATION" at 12382.02,6356.17 h60
  text "MIN. TRACK WIDTH:" at 11737.46,6224.05 h60
  text "8" at 12833.7,6224.05 h60
  text "MIL" at 12988.46,6224.05 h60
  text "MIN. CLEARANCE:" at 11737.46,6099.92 h60
  text "0.2" at 12773.7,6099.93 h60
  text "mm" at 12988.46,6099.92 h60
  text "MIN. VIA PAD SIZE:" at 11737.46,5975.8 h60
  text "24" at 12803.71,5975.8 h60
  text "MIL" at 12988.46,5975.8 h60
  text "0.05mm (2MIL)" at 12432.46,5845.9 h60
  text "MINIMUM ANNULAR RING" at 11408.23,5837.67 h60
  text "EXTERNAL" at 13140.46,5837.67 h60
  text "PER" at 11608.23,5727.55 h60
  text "IPC-D-275 CLASS 2 LEVEL C" at 11828.23,5727.54 h60
  text "MIL, HOLES" at 13316.46,5627.07 h60
  text "+/-" at 12924,5618.48 h60
  text "+/-" at 13778,5618.48 h60
  text "REGISTRATION TOLERANCES:" at 11408.23,5617.42 h60
  text "METAL" at 12608,5617.42 h60
  text "5" at 13184.2,5617.42 h60
  text "3" at 14017.2,5617.42 h60
  text "MIL" at 14133.46,5617.42 h60
  text "HOLE SIZE TOLERANCE (UNLESS OTHERWISE SPECIFIED):" at 11408.23,5519.1 h60
  text "+/-" at 13778,5516.23 h60
  text "3" at 14017.2,5515.17 h60
  text "MIL" at 14133.46,5515.17 h60
  text "MATERIAL:" at 11333.46,5377.52 h60
  text "FR-4 High Tg" at 12319.9,5249 h60
  text "X" at 12175.46,5241.01 h60
  text "FR-408" at 11754.46,5236.49 h60
  text "OTHER" at 13242.46,5236.49 h60
  text "62 MIL (1.6mm) +/-10%" at 12074.56,5093.46 h60
  text "X" at 11954.46,5091.01 h60
  text "THICKNESS:" at 11408.23,5085.24 h60
  text "OTHER" at 13359.46,5085.24 h60
  text "TOLERANCE:" at 11408.23,4946.92 h60
  text "X" at 12256.46,4946.92 h60
  text "ANSI IPC-6012 TYPE 3 CLASS 2" at 12434.48,4946.92 h60
  text "OTHER +/-" at 12434.46,4802.73 h60
  text "BOW & TWIST:" at 11408.23,4657.54 h60
  text "X" at 12256.46,4657.54 h60
  text "ANSI IPC-6012 TYPE 3 CLASS 2" at 12434.48,4657.54 h60
  text "OTHER +/-" at 12434.46,4510.85 h60
  text "DRILLING:" at 11333.46,4380.23 h60
  text "NC_DRILL FILES" at 13094.46,4275.04 h60
  text "REFERENCE:" at 11408.23,4271.1 h60
  text "X" at 12065.46,4271.01 h60
  text "AS SHOWN" at 12243.46,4271.1 h60
  text "X" at 12966.46,4271.1 h60
  text "OTHER" at 13392.46,4128.85 h60
  text "PTH COPPER THICKNESS:" at 11407.91,4125.32 h60
  text "X" at 12547.14,4125.32 h60
  text "20-30 um" at 12675.14,4125.32 h60
  text "BOARD FINISH:" at 11333.46,3977.73 h60
  text "SILKSCREEN:" at 11488.68,3867.6 h60
  text "X" at 12446.46,3867.6 h60
  text "TOP" at 12563.46,3867.6 h60
  text "X" at 12956.46,3867.6 h60
  text "BOTTOM" at 13074.46,3867.6 h60
  text "SILKSCREEN COLOR:" at 11488.68,3712.41 h60
  text "X" at 12445.46,3712.41 h60
  text "WHITE" at 12563.46,3712.41 h60
  text "OTHER" at 13074.46,3712.41 h60
  text "X" at 12576.46,3568.96 h60
  text "GREEN" at 12694.46,3568.96 h60
  text "OTHER" at 13312.46,3568.96 h60
  text "SOLDER RESIST COLOR:" at 11488.68,3562.1 h60
  text "X" at 12576.46,3414.71 h60
  text "MATTE" at 12694.46,3414.71 h60
  text "SEMI-GLOSS" at 13312,3414.07 h60
  text "IMMERSION GOLD (ENIG)" at 12394.46,3241.94 h60
  text "ENEPIG" at 13732,3234.72 h60
  text "SURFACE FINISH:" at 11333.46,3233.72 h60
  text "X" at 12216.46,3233.72 h60
  text "IMM. TIN/SILVER OR EQUIV" at 11663,3096.4 h60
  text "OTHER" at 13094.46,3092.47 h60
  text "ARRAY/PANEL:" at 11333.46,2937.09 h60
  text "CUT AND TRIM PER M1 BOARD OUTLINE" at 12394.46,2928.87 h60
  text "N.C. ROUTE" at 12394.46,2792.9 h60
  text "X" at 13082.46,2792.9 h60
  text "V. SCORE" at 13260.46,2792.9 h60
  text "CERTIFICATION:" at 11333.46,2663.77 h60
  text "MATERIALS AND WORKMANSHIP FOR ALL PCBS" at 12058.46,2663.77 h60
  text "TO MEET OR EXCEED THE REQUIREMENTS OF:" at 12058.46,2569.71 h60
  text "X" at 11695.97,2441.08 h60
  text "ANSI IPC-A-600F CLASS ->" at 11823.96,2441.08 h60
  text "X" at 13471.97,2441.08 h60
  text "2" at 13581.96,2441.08 h60
  text "1" at 13266.96,2439.58 h60
  text "3" at 13935.96,2439.58 h60
  text "X" at 12507.97,2293.39 h60
  text "RoHS" at 12635.96,2293.39 h60
  text "OTHER" at 13280.36,2293.39 h60
  text "PER ORDER" at 13677.42,2293.39 h60
  text "ALL BOARDS MUST MEET OR EXCEED UL94-V0 REQUIREMENTS." at 11361,2139.57 h60
  text "PCB MUST BEAR THE UL94V-0 UL REGISTERED MATERIAL ID NUMBER" at 11361,2023.5 h60
  text "ADDITIONAL REQUIREMENTS:" at 11333.46,1854.08 h60
  text "MICROSECTION:" at 11408.23,1746.95 h60
  text "YES" at 12313.96,1746.95 h60
  text "REQUIRED" at 13175.46,1602.62 h60
  text "BARE BOARD ELEC. TEST:" at 11408.23,1599.76 h60
  text "NONE" at 12713.96,1599.76 h60
  text "X" at 13057.46,1599.76 h60
  text "PER ORDER" at 13767.46,1599.76 h60
  text "XX MIL VIAS REQUIRE NON-CONDUCTIVE FILL AND PLANARIZE" at 11576.38,1394.82 h59
  text "XX MIL VIAS REQUIRE CONDUCTIVE FILL AND PLANARIZE" at 11584.38,1290.84 h60
  text "OUTER XX MIL TRACES REQUIRE 50 OHM SINGLE-ENDED IMPEDANCE" at 11583.39,1127.46 h58
  text "LAYER 2 & 3 (INNER LAYERS) XX MIL WIDE, XX MIL SPACE / TRACES REQUIRE 100 OHM DIFFERENTIAL IMPEDANCE" at 11575.39,891.74 h60
  text ".Layer_Name" at 577,-858.49 h60
M11 Gerber Information:
  lines w10: -292,-930.17 6308,-930.17 ; -292,-726.83 6310,-726.83 ; -292,-523.5 -292,-1133.5 3713,-1133.5 6310,-1133.5 6310,-523.5 -291.5,-523.5 -291.5,-1133.5 1284,-1133.5 ; 2173,-1133.5 2173,-523.5 ; 3440,-726.83 3440,-523.5 ; 4280,-726.83 4280,-523.5 ; 4902,-1140 4902,-937.17
  text "ALL ARTWORK VIEWED FROM TOP SIDE" at -228.5,-655.67 h60
  text "BOARD #:" at 2248,-655.67 h60
  text ".PRJ_Number" at 2793.5,-655.67 h60
  text "REV:" at 3638,-655.67 h60
  text ".PCB_Rev" at 3929.5,-655.67 h60
  text "SVN REV:" at 4476,-655.67 h60
  text ".VersionControl_RevNumber" at 4982,-655.67 h60
  text "LAYER NAME =" at -228.5,-858.49 h60
  text "TID #:" at 2248,-859 h60
  text ".TID" at 2793.5,-859 h60
  text "PLOT NAME =" at -228.5,-1064.34 h60
  text ".plot_File_Name" at 577,-1064.34 h60
  text "GENERATED    :" at 2250,-1064.34 h60
  text ".Print_Date" at 3119.5,-1064.34 h60
  text ".Print_Time" at 3848.5,-1064.34 h60
  text "TEXAS INSTRUMENTS" at 5113,-1064.34 h60
M12 Stackup:
  drawing of 191 lines, arcs and shapes, not listed
  text "Layer" at 9811.59,7717.44 h60
  text "Name" at 10221.51,7717.44 h60
  text "Material" at 11151.25,7717.44 h60
  text "Thickness" at 12011.02,7717.44 h60
  text "Constant" at 12660.85,7717.44 h60
  text "Board Layer Stack" at 13230.71,7717.44 h60
  text "1" at 9811.59,7597.44 h60
  text "Top Overlay" at 10221.51,7597.44 h60
  text "2" at 9811.59,7477.44 h60
  text "Top Solder" at 10221.51,7477.44 h60
  text "Solder Resist" at 11151.25,7477.44 h60
  text "0.40mil" at 12011.02,7477.44 h60
  text "3.5" at 12660.85,7477.44 h60
  text "3" at 9811.59,7357.44 h60
  text "Top Layer" at 10221.51,7357.44 h60
  text "Copper" at 11151.25,7357.44 h60
  text "1.40mil" at 12011.02,7357.44 h60
  text "4" at 9811.59,7237.44 h60
  text "Dielectric1" at 10221.51,7237.44 h60
  text "FR-4" at 11151.25,7237.44 h60
  text "59.20mil" at 12011.02,7237.44 h60
  text "4.8" at 12660.85,7237.44 h60
  text "5" at 9811.59,7117.44 h60
  text "Bottom Layer" at 10221.51,7117.44 h60
  text "Copper" at 11151.25,7117.44 h60
  text "1.40mil" at 12011.02,7117.44 h60
  text "6" at 9811.59,6997.44 h60
  text "Bottom Solder" at 10221.51,6997.44 h60
  text "Solder Resist" at 11151.25,6997.44 h60
  text "0.40mil" at 12011.02,6997.44 h60
  text "3.5" at 12660.85,6997.44 h60
  text "7" at 9811.59,6877.44 h60
  text "Bottom Overlay" at 10221.51,6877.44 h60
  text ".Layer_Name" at 577,-858.49 h60
M13 Component Bodies Top:
  text ".Layer_Name" at 577,-858.49 h60
M14 Component Bodies Bottom:
  text ".Layer_Name" at 577,-858.49 h60
M15 Courtyards Top:
  text ".Layer_Name" at 577,-858.49 h60
M16 Courtyards Bottom:
  text ".Layer_Name" at 577,-858.49 h60
Drill Drawing:
  circle w10: c5363.72,2959.32 r27.63
  lines w10: 5336.09,3056.02 5391.34,3056.02 5391.34,3111.27 5336.09,3111.27 5336.09,3056.02 ; 5336.09,3194.15 5349.9,3194.15 5363.72,3180.34 5377.53,3194.15 5391.34,3194.15 5377.53,3207.96 5391.34,3221.78 5377.53,3221.78 5363.72,3235.59 5349.9,3221.78 5336.09,3221.78 5349.9,3207.96 5336.09,3194.15 ; 5336.09,3359.91 5391.34,3359.91 5363.72,3304.66 5336.09,3359.91
  lines w12: 5286,2894.4 8517.49,2894.4 ; 5286,3391.68 8517.49,3391.68 ; 5623.86,2770.08 5623.86,3516 ; 5955.86,2770.08 5955.86,3516 ; 6592.43,2770.08 6592.43,3516 ; 6851.57,2770.08 6851.57,3516 ; 7226.72,2770.08 7226.72,3516 ; 7951.05,2770.08 7951.05,3516 ; 5286,2770.08 8517.49,2770.08 8517.49,3516 5286,3516 5286,2770.08
  text "Symbol" at 5360.59,3428.98 h72
  text "Quantity" at 5661.16,3428.98 h72
  text "Finished Hole Size" at 5993.16,3428.98 h72
  text "Plated" at 6629.72,3428.98 h72
  text "Hole Type" at 6888.86,3428.98 h72
  text "Drill Layer Pair" at 7264.02,3428.98 h72
  text "Hole Tolerance" at 7988.35,3428.98 h72
  text "4" at 5661.16,3304.66 h60
  text "7.87mil (0.200mm)" at 5993.16,3304.66 h60
  text "PTH" at 6629.72,3304.66 h60
  text "Round" at 6888.86,3304.66 h60
  text "Top Layer - Bottom Layer" at 7264.02,3304.66 h60
  text "102" at 5661.16,3180.34 h60
  text "10.00mil (0.254mm)" at 5993.16,3180.34 h60
  text "PTH" at 6629.72,3180.34 h60
  text "Round" at 6888.86,3180.34 h60
  text "Top Layer - Bottom Layer" at 7264.02,3180.34 h60
  text "9" at 5661.16,3056.02 h60
  text "40.00mil (1.016mm)" at 5993.16,3056.02 h60
  text "PTH" at 6629.72,3056.02 h60
  text "Round" at 6888.86,3056.02 h60
  text "Top Layer - Bottom Layer" at 7264.02,3056.02 h60
  text "6" at 5661.16,2931.7 h60
  text "43.31mil (1.100mm)" at 5993.16,2931.7 h60
  text "PTH" at 6629.72,2931.7 h60
  text "Round" at 6888.86,2931.7 h60
  text "Top Layer - Bottom Layer" at 7264.02,2931.7 h60
  text "121 Total" at 5661.16,2807.38 h60
  text ".Layer_Name" at 577,-858.49 h60
M17 Embedded Cavity:
  text ".Layer_Name" at 577,-858.49 h60
M18 Embedded Assembly:
  text ".Layer_Name" at 577,-858.49 h60
M19 Embedded Keepout:
  text ".Layer_Name" at 577,-858.49 h60

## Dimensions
0,-400 to 1000,-400 on M2 Board Dimensions
0,0 to 0,1102.36 on M2 Board Dimensions
0,0 to 2440.94,0 on M2 Board Dimensions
